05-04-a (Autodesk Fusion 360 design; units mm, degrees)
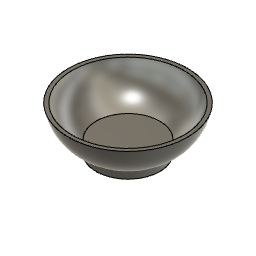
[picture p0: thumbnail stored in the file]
sketch "スケッチ1" plane through (0, 0, 0) normal (0, 0, 1) x axis (1, 0, 0)
  line L1 (-7, -2) -> (-8, -2)
  line L2 (-7, 0) -> (-7, -2)
  line L3 (-8, 0) -> (-7, 0)
  line L4 (-8, -2) -> (-8, 0)
  line L5 (0, 22.5) -> (0, 1.75)
  point P1 (0, 0)
  point P4 (-7, 0)
  point P2 (-8, -2)
  point P3 (-7, -2)
  point P5 (-8, 0)
  horizontal L1
  vertical L2
  horizontal L3
  vertical L4
  horizontal P1 P4
  dimension "d1" distance P2 P3 = 1
  dimension "d2" distance P2 P5 = 2
  dimension "d3" = 16
revolve "回転1" sketch "スケッチ1" AlongAngle 360
sketch "スケッチ2" plane through (0, 0, 0) normal (0, 0, 1) x axis (1, 0, 0)
  line L1 (-8, 0) -> (0, 0)
  line L2 (-8, 1) -> (-8, 0)
  line L3 (0, 1) -> (-8, 1)
  line L4 (0, 0) -> (0, 1)
  line L5 (-8, -2) -> (-8, 0)
  line L6 (8, 0) -> (8, -2)
  point P1 (0, 0)
  point P2 (0, 0)
  point P3 (-8, 0)
  point P4 (-8, 1)
  horizontal L1
  vertical L2
  horizontal L3
  vertical L4
  coincident P1 P2
  collinear L2 L5
  dimension "d5" distance P3 P4 = 1
revolve "回転2" sketch "スケッチ2" AlongAngle 360
sketch "スケッチ3" plane through (0, 0, 0) normal (0, 0, 1) x axis (1, 0, 0)
  line L1 (-14.0784, 9) -> (-15, 9)
  line L2 (-8, 0) -> (-8, 1)
  line L3 (-8, -2) -> (-8, 1)
  line L4 (8, 1) -> (8, -2)
  line L5 (0, 22.5) -> (0, 1.75)
  arc A1 centre (-3.1649, 10.9828) radius 11.0921 clockwise from (-8, 1) to (-14.0784, 9)
  arc A2 centre (-3.1649, 10.9828) radius 12 clockwise from (-8, 0) to (-15, 9)
  point P3 (-8, 1)
  point P8 (-8, 1)
  point P1 (0, 0)
  point P6 (-8, 0)
  vertical L2
  horizontal L1
  concentric A1 A2
  coincident P3 P8
  horizontal P1 P6
  dimension "d7" distance P1 L1 = 9
  dimension "d8" radius A2 = 12
  dimension "d9" = 30
revolve "回転3" sketch "スケッチ3" AlongAngle 360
